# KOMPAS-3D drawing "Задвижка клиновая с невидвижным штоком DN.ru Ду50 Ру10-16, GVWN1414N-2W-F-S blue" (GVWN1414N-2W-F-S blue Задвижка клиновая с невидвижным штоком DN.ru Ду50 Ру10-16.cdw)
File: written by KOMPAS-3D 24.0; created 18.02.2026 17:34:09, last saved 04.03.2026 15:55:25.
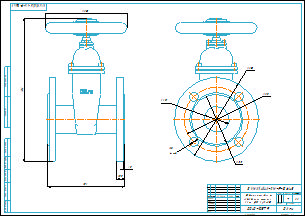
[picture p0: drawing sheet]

Document properties: Автор: R2D2; Форматы листов документа: A2; Полное имя файла: GVWN1414N-2W-F-S blue Задвижка клиновая с невидвижным штоком DN.ru Ду50 Ру10-16.m3d; Масса: 7; Наименование: Задвижка клиновая с невидвижным штоком DN.ru Ду50 Ру10-16; Количество листов документа: 1; Примечание: D040-10579

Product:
- Part/product: Задвижка клиновая с невидвижным штоком DN.ru Ду50 Ру10-16  | designation GVWN1414N-2W-F-S blue
    Масса: 7
    Раздел спецификации: Прочие изделия
    Примечание: D040-10579

Views: Вид 1, Спереди, Проекционный вид 2
Referenced files in E:\Работа\Зайцев\GVWN1414N-2W-F-S blue Задвижка клиновая с невидвижным штоком DN.ru Ду40-300 Ру10-16\DN50\: GVWN1414N-2W-F-S blue Задвижка клиновая с невидвижным штоком DN.ru Ду50 Ру10-16.m3d
Referenced files in E:\Работа\Зайцев\Для компаса\: чертеж DN.ru А3.cdt
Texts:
  GVWN1414N-2W-F-S blue
  чертеж DN.ru А3.cdt
  Задвижка клиновая с
  невидвижным штоком
  DN.ru Ду50 Ру10-16
  Задвижка клиновая с невидвижным штоком DN.ru Ду50 Ру10-16
  GVWN1414N-2W-F-S blue Задвижка клиновая с невидвижным штоком DN.ru Ду50 Ру10-16
Dimensions and other numbers on the sheet: 0; 3; 2; 4; 150; 15,5; 2,5; 280; 160; 165; 125; 99; 50; 18; 4 отв.; 1:1; 1; 7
